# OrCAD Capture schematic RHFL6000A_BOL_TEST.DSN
size A
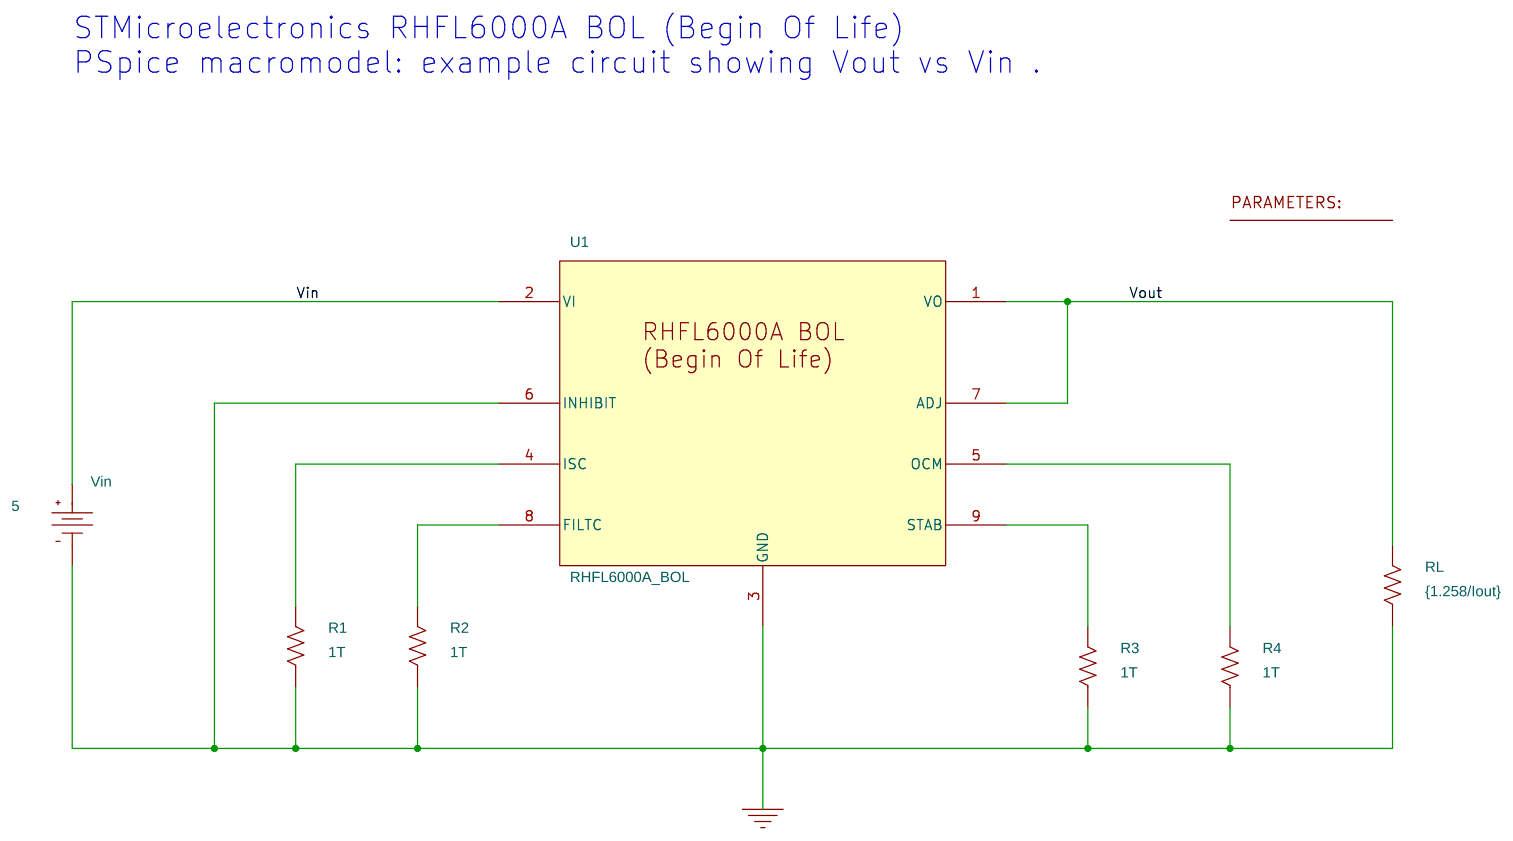
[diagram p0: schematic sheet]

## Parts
1  PARAM
R1  1T  [AX/RC05]
R2  1T  [AX/RC05]
R3  1T  [AX/RC05]
R4  1T  [AX/RC05]
RL  {1.258/Iout}  [AX/RC05]
U1  RHFL6000A_BOL
Vin  VDC

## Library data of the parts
1 = PARAM
R1-R4 RL = R
U1 = RHFL6000A_BOL
Vin = VDC: DC: 5

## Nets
Vin: U1.2(VI) Vin.0(+)
0: R1.1 R2.1 R3.1 R4.1 RL.1 U1.3(GND) U1.6(INHIBIT) Vin.1(-)
Vout: RL.2 U1.1(VO) U1.7(ADJ)
N00259: R1.2 U1.4(ISC)
N00308: R2.2 U1.8(FILTC)
N00356: R3.2 U1.9(STAB)
N00414: R4.2 U1.5(OCM)

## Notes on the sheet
- STMicroelectronics RHFL6000A BOL (Begin Of Life)
  PSpice macromodel: example circuit showing Vout vs Vin .
